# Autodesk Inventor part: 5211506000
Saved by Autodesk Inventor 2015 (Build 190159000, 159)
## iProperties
Created: 2020-07
Part Number: 5211506000
Checked By: TraceParts S.A.
Material: Generic
Catalog Web Link: www.traceparts.com
Document SubType Name: Modeling
Designer: TraceParts
Density: 1 g/cm^3
Appearance: Default
Company: TraceParts S.A.
Author: TraceParts
REFERENCE: 5211506000
DESIGN: TDM-200 (230V 50) RE - 5211506000
SUPPLIER: Soler & Palau
TraceParts.PartNumber: 10-20122018-119657
TraceParts.PartTitle: TDM
TraceParts.InstanceId: 10-20122018-119657DJ1TABMT3LWSQOHIOFDSYV98C
TraceParts.PartStatus: Published
TraceParts.PartVersion: 1.0.2
TRACEPARTS: TRACEPARTS
TraceParts.PartLanguage: en
TraceParts.ClassPath: SOLER_PALAU:10-20122018-119657
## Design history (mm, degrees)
feature "5211506000"
body "Solid1"
